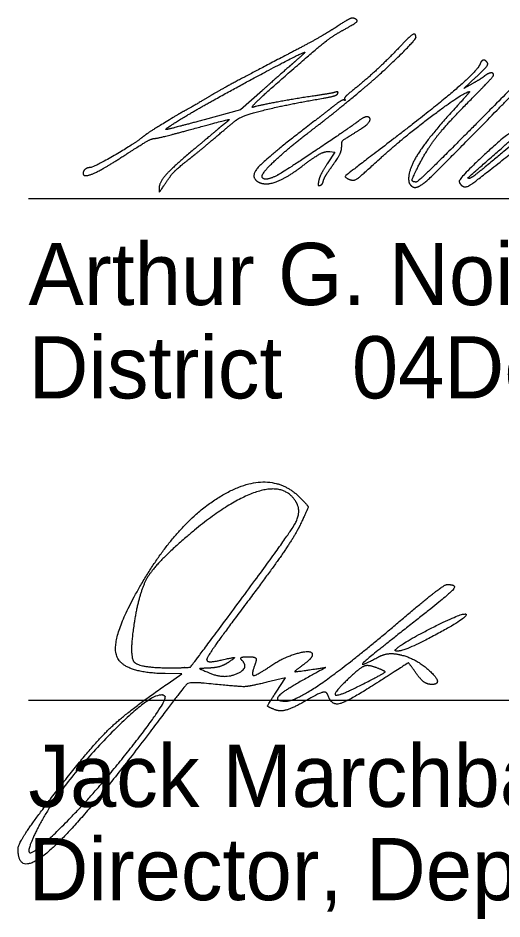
# Model space of a CAD drawing. Extents: x 25.6 to 80.6, y 0.2 to 24.5.
# Drawn here: x 60.017 to 61.107, y 7.535 to 9.563 of the extents above; entities that cross this region are included whole.
import ezdxf

# ---------------------------------------------------------------- set-up
doc = ezdxf.new("R2010")
doc.units = 0
doc.layers.add('SH_Data', color=7, linetype='Continuous')
doc.layers.add('SH_Text', color=7, linetype='Continuous')

msp = doc.modelspace()

# ---------------------------------------------------------------- linework, layer by layer
at = {"layer": 'SH_Data'}
for p, q in [((60.0407, 9.1565), (63.5407, 9.1565)), ((60.0407, 8.0271), (63.5407, 8.0271))]:
    msp.add_line(p, q, dxfattribs=at)
at = {"layer": 'SH_Text'}
for p, q in [((60.503, 8.2321), (60.503, 8.2321)), ((60.8683, 8.1423), (60.8683, 8.1423)), ((60.8235, 8.1006), (60.8235, 8.1006))]:
    msp.add_line(p, q, dxfattribs=at)
for points in [[(61.0411, 9.4154), (61.0208, 9.4039), (61.049, 9.4302)], [(60.5674, 9.3997), (60.5178, 9.3556), (60.4363, 9.3336)], [(60.7196, 9.262), (60.7302, 9.2607), (60.7135, 9.2348)], [(60.3553, 8.0652), (60.386, 8.0864), (60.3482, 8.087)], [(60.5983, 8.0453), (60.6195, 8.0777), (60.5777, 8.0676)]]:
    msp.add_lwpolyline(points, dxfattribs=at)
for points in [[(60.773, 9.5623), (60.7695, 9.5636), (60.7539, 9.5558), (60.7355, 9.5434)], [(60.7518, 9.5369), (60.7771, 9.5508), (60.7834, 9.5583), (60.773, 9.5623)], [(61.2882, 9.5534), (61.2499, 9.5251), (61.2094, 9.4868), (61.0798, 9.3558)], [(60.7355, 9.5434), (60.7183, 9.5318), (60.6673, 9.5031), (60.6222, 9.4796)], [(60.6294, 9.4414), (60.6941, 9.4978), (60.726, 9.5227), (60.7518, 9.5369)], [(60.7883, 9.3985), (60.8261, 9.4297), (60.9129, 9.5136), (60.9129, 9.519)], [(60.9129, 9.519), (60.9129, 9.5298), (60.8982, 9.5209), (60.8751, 9.4962)], [(60.8751, 9.4962), (60.8499, 9.4692), (60.794, 9.4179), (60.7654, 9.3954)], [(61.0958, 9.3552), (61.1683, 9.4293), (61.2368, 9.4969), (61.2479, 9.5055)], [(60.6222, 9.4796), (60.5462, 9.4401), (60.4672, 9.3977), (60.4528, 9.3889)], [(60.4588, 9.3785), (60.5358, 9.4213), (60.6612, 9.4872), (60.6628, 9.4856)], [(60.6628, 9.4856), (60.6634, 9.485), (60.6533, 9.4754), (60.6404, 9.4642)], [(60.6404, 9.4642), (60.6275, 9.453), (60.5946, 9.424), (60.5674, 9.3997)], [(61.0574, 9.4591), (61.0521, 9.4449), (60.9582, 9.3636), (60.8635, 9.2912)], [(61.049, 9.4302), (61.0666, 9.4466), (61.0761, 9.4584), (61.0742, 9.4614)], [(61.0742, 9.4614), (61.0698, 9.4686), (61.0604, 9.4673), (61.0574, 9.4591)], [(60.5474, 9.3619), (60.5389, 9.3591), (60.5745, 9.3937), (60.6294, 9.4414)], [(61.0399, 9.3824), (61.0663, 9.409), (61.088, 9.4324), (61.088, 9.4343)], [(61.0679, 9.4323), (61.0644, 9.4294), (61.0523, 9.4217), (61.0411, 9.4154)], [(61.088, 9.4343), (61.088, 9.4396), (61.0751, 9.4384), (61.0679, 9.4323)], [(60.4528, 9.3889), (60.4358, 9.3785), (60.3908, 9.3523), (60.3898, 9.3523)], [(60.6686, 9.3028), (60.7076, 9.3327), (60.7352, 9.3548), (60.7883, 9.3985)], [(60.7312, 9.3955), (60.727, 9.3942), (60.7052, 9.3904), (60.6827, 9.3871)], [(60.7039, 9.382), (60.7219, 9.3851), (60.736, 9.3896), (60.737, 9.3926)], [(60.737, 9.3926), (60.7382, 9.3962), (60.7363, 9.3971), (60.7312, 9.3955)], [(60.7654, 9.3954), (60.7571, 9.3889), (60.7514, 9.3818), (60.7528, 9.3795)], [(60.831, 9.2451), (60.8821, 9.292), (61.0222, 9.397), (61.0335, 9.397)], [(61.0335, 9.397), (61.0347, 9.397), (61.0226, 9.3828), (61.0066, 9.3655)], [(60.35, 9.3115), (60.3455, 9.3115), (60.4119, 9.3524), (60.4588, 9.3785)], [(60.5118, 9.3351), (60.5237, 9.3437), (60.6288, 9.3694), (60.7039, 9.382)], [(60.6827, 9.3871), (60.6393, 9.3806), (60.5591, 9.3657), (60.5474, 9.3619)], [(60.7515, 9.3778), (60.7494, 9.3791), (60.7386, 9.373), (60.7275, 9.3641)], [(60.7528, 9.3795), (60.7542, 9.3773), (60.7536, 9.3765), (60.7515, 9.3778)], [(60.9184, 9.229), (60.9381, 9.268), (60.9838, 9.3258), (61.0399, 9.3824)], [(60.3898, 9.3523), (60.3892, 9.3523), (60.3788, 9.3462), (60.3668, 9.3388)], [(60.7275, 9.3641), (60.7164, 9.3553), (60.6972, 9.3404), (60.6849, 9.3309)], [(61.0066, 9.3655), (60.9475, 9.3016), (60.8966, 9.2252), (60.8966, 9.2005)], [(60.9114, 9.1813), (60.9218, 9.1813), (60.9673, 9.2242), (61.0958, 9.3552)], [(61.0798, 9.3558), (60.9914, 9.2664), (60.9168, 9.1933), (60.9141, 9.1934)], [(60.3668, 9.3388), (60.3154, 9.3073), (60.3079, 9.3024), (60.2917, 9.29)], [(60.4363, 9.3336), (60.3915, 9.3215), (60.3527, 9.3115), (60.35, 9.3115)], [(60.4052, 9.3115), (60.486, 9.3334), (60.4963, 9.3353), (60.4833, 9.3255)], [(60.4635, 9.2955), (60.4834, 9.3125), (60.5051, 9.3303), (60.5118, 9.3351)], [(60.6849, 9.3309), (60.5801, 9.2506), (60.5378, 9.2046), (60.5586, 9.1935)], [(60.7859, 9.3323), (60.7673, 9.3179), (60.6134, 9.2149), (60.6006, 9.2084)], [(60.8019, 9.3223), (60.8146, 9.3346), (60.8004, 9.3435), (60.7859, 9.3323)], [(60.3224, 9.2912), (60.3266, 9.2912), (60.3639, 9.3003), (60.4052, 9.3115)], [(60.4671, 9.3123), (60.4626, 9.3085), (60.4367, 9.2866), (60.4095, 9.2637)], [(60.4833, 9.3255), (60.4789, 9.3221), (60.4715, 9.3162), (60.4671, 9.3123)], [(60.7714, 9.3019), (60.7854, 9.3104), (60.7991, 9.3195), (60.8019, 9.3223)], [(61.1988, 9.3138), (61.1781, 9.3133), (61.1467, 9.2923), (61.066, 9.225)], [(60.2917, 9.29), (60.2725, 9.2753), (60.1865, 9.226), (60.1801, 9.226)], [(60.2679, 9.2606), (60.2937, 9.2774), (60.3182, 9.2912), (60.3224, 9.2912)], [(60.4085, 9.25), (60.4189, 9.2581), (60.4436, 9.2786), (60.4635, 9.2955)], [(60.5668, 9.2067), (60.5668, 9.2145), (60.625, 9.2694), (60.6686, 9.3028)], [(60.746, 9.2764), (60.746, 9.2845), (60.7512, 9.2897), (60.7714, 9.3019)], [(60.8635, 9.2912), (60.7582, 9.2107), (60.7511, 9.2041), (60.764, 9.1991)], [(61.1263, 9.3034), (61.1191, 9.3034), (61.0107, 9.2021), (61.0106, 9.1953)], [(61.0933, 9.2585), (61.1313, 9.2917), (61.1399, 9.3034), (61.1263, 9.3034)], [(60.7196, 9.2225), (60.7381, 9.2484), (60.746, 9.2645), (60.746, 9.2764)], [(61.1024, 9.2385), (61.1484, 9.2753), (61.1543, 9.2789), (61.1588, 9.2727)], [(60.2019, 9.2199), (60.2124, 9.2254), (60.242, 9.2438), (60.2679, 9.2606)], [(60.4095, 9.2637), (60.364, 9.2255), (60.3347, 9.1921), (60.3347, 9.1785)], [(60.349, 9.1904), (60.3612, 9.2091), (60.3788, 9.2267), (60.4085, 9.25)], [(60.6523, 9.2257), (60.6828, 9.2492), (60.7089, 9.2633), (60.7196, 9.262)], [(61.0334, 9.2017), (61.0287, 9.2019), (61.0301, 9.2032), (61.0933, 9.2585)], [(60.7135, 9.2348), (60.7043, 9.2205), (60.6956, 9.2034), (60.6943, 9.1966)], [(60.764, 9.1991), (60.7733, 9.1956), (60.7877, 9.2055), (60.831, 9.2451)], [(60.9141, 9.1934), (60.9039, 9.1936), (60.9049, 9.2022), (60.9184, 9.229)], [(61.0153, 9.1864), (61.0225, 9.1791), (61.0442, 9.1922), (61.1024, 9.2385)], [(60.1801, 9.226), (60.1732, 9.226), (60.1637, 9.2185), (60.1637, 9.213)], [(60.1637, 9.213), (60.1637, 9.2065), (60.1833, 9.21), (60.2019, 9.2199)], [(60.6006, 9.2084), (60.5852, 9.2004), (60.5668, 9.1995), (60.5668, 9.2067)], [(60.5772, 9.1894), (60.5897, 9.1894), (60.6311, 9.2094), (60.6523, 9.2257)], [(60.7047, 9.1958), (60.7055, 9.2001), (60.7122, 9.2121), (60.7196, 9.2225)], [(61.066, 9.225), (61.0505, 9.2122), (61.0358, 9.2017), (61.0334, 9.2017)], [(60.3347, 9.1785), (60.3347, 9.1701), (60.3369, 9.1719), (60.349, 9.1904)], [(60.5586, 9.1935), (60.5628, 9.1912), (60.5712, 9.1894), (60.5772, 9.1894)], [(60.6943, 9.1966), (60.6924, 9.1871), (60.6931, 9.1847), (60.6975, 9.1861)], [(60.6975, 9.1861), (60.7006, 9.1872), (60.7039, 9.1916), (60.7047, 9.1958)], [(60.8966, 9.2005), (60.8966, 9.1953), (60.8988, 9.1888), (60.9015, 9.1861)], [(60.9015, 9.1861), (60.9042, 9.1835), (60.9087, 9.1813), (60.9114, 9.1813)], [(61.0106, 9.1953), (61.0106, 9.193), (61.0127, 9.1889), (61.0153, 9.1864)], [(60.2917, 8.2829), (60.3779, 8.4332), (60.586, 8.5493), (60.6517, 8.4836)], [(60.6427, 8.4744), (60.6168, 8.5164), (60.4907, 8.4753), (60.3953, 8.3937)], [(60.6517, 8.4836), (60.6705, 8.4648), (60.6705, 8.4598), (60.6522, 8.4214)], [(60.503, 8.2321), (60.6243, 8.3956), (60.6568, 8.4518), (60.6427, 8.4744)], [(60.6522, 8.4214), (60.6412, 8.3984), (60.5895, 8.3228), (60.5373, 8.2535)], [(60.3953, 8.3937), (60.3287, 8.3366), (60.2899, 8.2725), (60.2788, 8.2013)], [(60.3482, 8.087), (60.2503, 8.0887), (60.2269, 8.1699), (60.2917, 8.2829)], [(60.8818, 8.2094), (60.9322, 8.2522), (60.9777, 8.2874), (60.9829, 8.2875)], [(60.9829, 8.2875), (61.0078, 8.288), (60.9844, 8.2624), (60.8985, 8.1952)], [(60.5373, 8.2535), (60.485, 8.1841), (60.4423, 8.1234), (60.4423, 8.1187)], [(60.3568, 8.1002), (60.4035, 8.1002), (60.4081, 8.1043), (60.503, 8.2321)], [(60.8683, 8.1423), (60.8887, 8.1601), (61.0208, 8.2259), (61.0259, 8.2207)], [(61.0259, 8.2207), (61.0321, 8.2146), (60.8895, 8.1377), (60.8718, 8.1377)], [(60.2788, 8.2013), (60.2674, 8.1279), (60.2888, 8.1002), (60.3568, 8.1002)], [(60.6204, 8.0252), (60.6435, 8.0252), (60.7695, 8.114), (60.8818, 8.2094)], [(60.8985, 8.1952), (60.8053, 8.1222), (60.7838, 8.1006), (60.8278, 8.1241)], [(60.5864, 8.1046), (60.6153, 8.1244), (60.6798, 8.1419), (60.6798, 8.1299)], [(60.8278, 8.1241), (60.8404, 8.1309), (60.8643, 8.133), (60.8809, 8.1288)], [(60.8718, 8.1377), (60.867, 8.1377), (60.8655, 8.1397), (60.8683, 8.1423)], [(60.4423, 8.1187), (60.4423, 8.1139), (60.4577, 8.1136), (60.4767, 8.118)], [(60.4923, 8.1133), (60.482, 8.1063), (60.4623, 8.1001), (60.4485, 8.0996)], [(60.4527, 8.0869), (60.4826, 8.0749), (60.5388, 8.0995), (60.5214, 8.1169)], [(60.4767, 8.118), (60.5022, 8.1239), (60.5062, 8.1227), (60.4923, 8.1133)], [(60.5214, 8.1169), (60.5168, 8.1215), (60.5231, 8.1252), (60.5353, 8.1252)], [(60.5353, 8.1252), (60.5499, 8.1252), (60.555, 8.1188), (60.5503, 8.1064)], [(60.6798, 8.1299), (60.6798, 8.1254), (60.67, 8.1146), (60.6581, 8.1059)], [(60.9139, 8.0874), (60.8971, 8.1114), (60.895, 8.111), (60.8293, 8.0686)], [(60.8809, 8.1288), (60.917, 8.1196), (60.9753, 8.0627), (60.9486, 8.0627)], [(60.4485, 8.0996), (60.4261, 8.0987), (60.4266, 8.0974), (60.4527, 8.0869)], [(60.5503, 8.1064), (60.5413, 8.0832), (60.5542, 8.0825), (60.5864, 8.1046)], [(60.6581, 8.1059), (60.6392, 8.0921), (60.6412, 8.0908), (60.6738, 8.0957)], [(60.6738, 8.0957), (60.7105, 8.1012), (60.7104, 8.101), (60.665, 8.0759)], [(60.8235, 8.1006), (60.8063, 8.1069), (60.7898, 8.1018), (60.7704, 8.0841)], [(60.7954, 8.0643), (60.8418, 8.088), (60.8453, 8.0926), (60.8235, 8.1006)], [(60.665, 8.0759), (60.6139, 8.0477), (60.5942, 8.0252), (60.6204, 8.0252)], [(60.7704, 8.0841), (60.7261, 8.0436), (60.7374, 8.0347), (60.7954, 8.0643)], [(60.9486, 8.0627), (60.939, 8.0627), (60.9234, 8.0738), (60.9139, 8.0874)], [(60.1044, 7.823), (60.182, 7.9234), (60.2621, 8.0007), (60.3553, 8.0652)], [(60.4365, 8.0653), (60.4031, 8.0686), (60.3914, 8.0581), (60.3147, 7.9564)], [(60.5777, 8.0676), (60.5374, 8.0578), (60.5151, 8.0575), (60.4365, 8.0653)], [(60.8293, 8.0686), (60.7604, 8.0243), (60.7229, 8.0145), (60.7148, 8.0389)], [(60.3482, 8.0359), (60.3273, 8.0568), (60.1088, 7.8312), (60.0625, 7.7408)], [(60.1326, 7.7596), (60.2002, 7.8286), (60.3559, 8.0282), (60.3482, 8.0359)], [(60.5971, 8.0053), (60.5789, 8.0122), (60.579, 8.0159), (60.5983, 8.0453)], [(60.7148, 8.0389), (60.7119, 8.0474), (60.6927, 8.0422), (60.6636, 8.0251)], [(60.6636, 8.0251), (60.638, 8.01), (60.6081, 8.0011), (60.5971, 8.0053)], [(60.3147, 7.9564), (60.1624, 7.7544), (60.0173, 7.6257), (60.0173, 7.6927)], [(60.0173, 7.6927), (60.0173, 7.7024), (60.0565, 7.761), (60.1044, 7.823)], [(60.0625, 7.7408), (60.0312, 7.6799), (60.0629, 7.6883), (60.1326, 7.7596)]]:
    msp.add_open_spline(points, degree=2, dxfattribs=at)

# ---------------------------------------------------------------- texts
for s, p in [('Arthur G. Noirot Jr., P.E.', (60.0407, 8.9165)), ('District       Deputy Director', (60.0407, 8.7065)), ('              04', (60.0407, 8.7065)), ('Jack Marchbanks, PhD', (60.0407, 7.7871)), ('Director, Department of Transportation', (60.0407, 7.5771))]:
    msp.add_text(s, height=0.14, dxfattribs=at).set_placement(p)

doc.saveas('drawing.dxf')
